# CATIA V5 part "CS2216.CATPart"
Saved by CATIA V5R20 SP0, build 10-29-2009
Part number: CS2216
Revision: 7
Definition: design
Nomenclature: CS2216
Source: made
Description: NOT SPECIFIED
Bounding box of the stored display mesh (mm): x -15 to 15, y -15 to 15, z -28 to 7.5
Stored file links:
  C:\Users\Raffaele\Desktop\3D X SITO CF\BOLEX\20-TILTED COLUMN SUPPORT\CS2216.CATPart
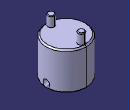
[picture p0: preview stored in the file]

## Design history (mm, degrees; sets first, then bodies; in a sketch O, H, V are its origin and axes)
Body1 "MANIFOLD_SOLID_BREP #724" (main body)
  Solid1: solid without history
